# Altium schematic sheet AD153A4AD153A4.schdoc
size 127 x 101 mm
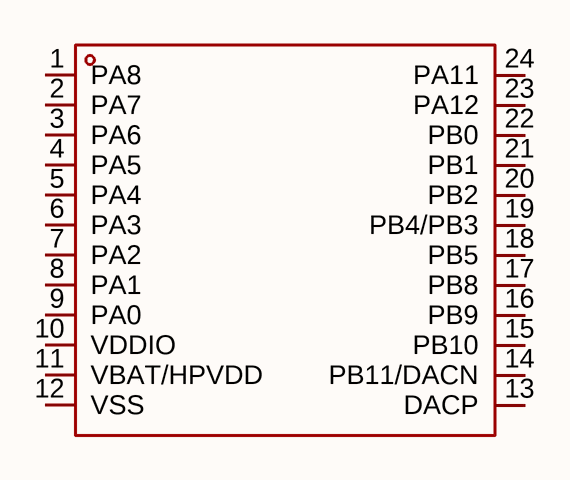
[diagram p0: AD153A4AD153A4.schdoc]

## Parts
U?  ad153a4  [QSOP-24_L8.7-W3.9-P0.64-LS6.0-BL]  (value not drawn)

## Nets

Not connected (* = marked no-connect by the designer): U? 1(PA8) 2(PA7) 3(PA6) 4(PA5) 5(PA4) 6(PA3) 7(PA2) 8(PA1) 9(PA0) 10(VDDIO) 11(VBAT/HPVDD) 12(VSS) 13(DACP) 14(PB11/DACN) 15(PB10) 16(PB9) 17(PB8) 18(PB5) 19(PB4/PB3) 20(PB2) 21(PB1) 22(PB0) 23(PA12) 24(PA11)

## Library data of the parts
U? = ad153a4: CPU内核:-;CPU最大主频:120MHz;CPU位数:32 Bit;; Manufacturer: JL(杰理); AddInBom: yes; ModelId: 0d5eb4aa1e904faba2151708d4bb6535; ModelTransform: 339.369,237.007,0,0,0,0,0,0,0; CPU Maximum Speed: 120MHz; Core Size: 32 Bit; Number of I/O: 20; ADC (Bit): 10bit; Voltage - Supply: 2V~5.5V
